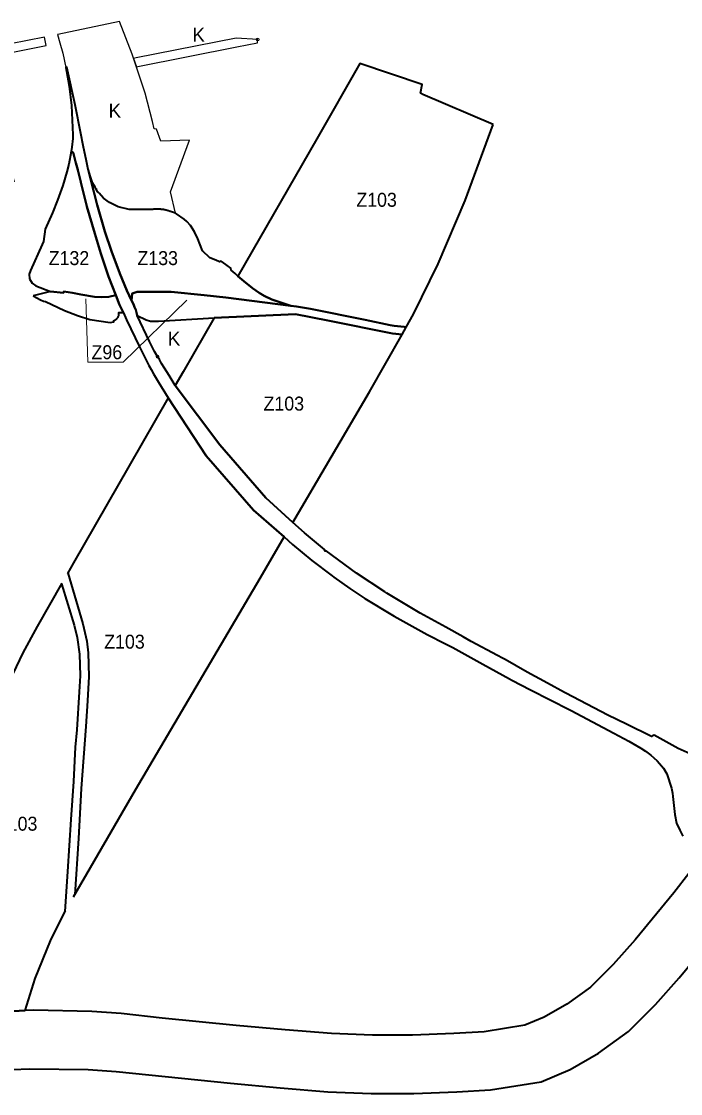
# Model space of a CAD drawing. Extents: x -650276 to -642489, y -1074311 to -1066658.
# Drawn here: x -647871 to -646740, y -1069094 to -1067254 of the extents above; entities that cross this region are included whole.
import ezdxf

# ---------------------------------------------------------------- set-up
doc = ezdxf.new("R2010")
doc.units = 0
doc.header["$LTSCALE"] = 9.6
doc.header["$PDMODE"] = 32
doc.header["$PDSIZE"] = 4.8
for name, color, linetype, lineweight in [('44', 7, 'Continuous', 40), ('47', 7, 'Continuous', 13), ('48', 7, 'Continuous', 13)]:
    doc.layers.add(name, color=color, linetype=linetype, lineweight=lineweight)

msp = doc.modelspace()

# ---------------------------------------------------------------- linework, layer by layer
at = {"layer": '44'}
for p, q in [((-647489.3, -1067700.07), (-647474.13, -1067711.81)), ((-647540.208, -1067762.876), (-647400.63, -1067756.19))]:
    msp.add_line(p, q, dxfattribs=at)
for points in [[(-647606.818, -1067879.061), (-647617.25, -1067861.95), (-647625.37, -1067848.86), (-647630.3, -1067841.02), (-647633.69, -1067834.31), (-647637.21, -1067829.29), (-647642.29, -1067820.76), (-647650.8, -1067803.28), (-647672.05, -1067758.98), (-647673.47, -1067753.48), (-647673.47, -1067753.48), (-647674.67, -1067748.73), (-647676.47, -1067744.5), (-647678.66, -1067739.38), (-647681.91, -1067732.74), (-647690.09, -1067716.05), (-647702.04, -1067686.86), (-647715.92, -1067648.12), (-647727.37, -1067614.33), (-647740.49, -1067568.67), (-647751.41, -1067526.58), (-647756.55, -1067505.32), (-647759.16, -1067494.01), (-647764.89, -1067466.64), (-647768.5, -1067446.04), (-647778.78, -1067397.1), (-647792.52, -1067332.74), (-647794.54, -1067333.14), (-647788.77, -1067365.03), (-647784.55, -1067398.01), (-647782.39, -1067448.34), (-647782.5, -1067455.11), (-647784.36, -1067469.6), (-647785.64, -1067477.02), (-647781.85, -1067479.19), (-647777.55, -1067496.95), (-647773.96, -1067508.48), (-647768.5, -1067529.75), (-647758.25, -1067571.79), (-647744.61, -1067617.96), (-647734.63, -1067652.57), (-647721.05, -1067691.73), (-647708.71, -1067723.99), (-647702.21, -1067740.43), (-647699.89, -1067745.24), (-647697.85, -1067749.46), (-647695.71, -1067753.9), (-647690.19, -1067766.37), (-647668.13, -1067812.76), (-647651.94, -1067844.36), (-647648.33, -1067851.17), (-647643.83, -1067859.13), (-647635.77, -1067873.43), (-647618.773, -1067899.914)], [(-647185.93, -1067377.38), (-647183.09, -1067362.16), (-647289.924, -1067326.309), (-647364.024, -1067455.561), (-647499.095, -1067691.163), (-647489.3, -1067700.07)], [(-647061.252, -1067430.908), (-647181.878, -1067379.12), (-647185.93, -1067377.38)], [(-647155.592, -1067670.17), (-647108.971, -1067561.55), (-647061.252, -1067430.908)], [(-647708.71, -1067723.99), (-647721.05, -1067691.73), (-647734.63, -1067652.57), (-647744.61, -1067617.96), (-647758.25, -1067571.79), (-647768.5, -1067529.75), (-647773.96, -1067508.48), (-647777.55, -1067496.95), (-647781.85, -1067479.19), (-647785.64, -1067477.02), (-647789.39, -1067498.84), (-647792.54, -1067511.85), (-647799.39, -1067535.48)], [(-647799.39, -1067535.48), (-647808.71, -1067561.03), (-647817.59, -1067582.4)], [(-647739.417, -1067547.032), (-647740.122, -1067546.264), (-647744.43, -1067538.658), (-647751.41, -1067526.58), (-647740.49, -1067568.67), (-647727.37, -1067614.33), (-647715.92, -1067648.12)], [(-647737.867, -1067548.624), (-647738.148, -1067548.252), (-647738.514, -1067547.9), (-647739.417, -1067547.032)], [(-647650.7, -1067576.803), (-647651.205, -1067576.828), (-647651.711, -1067576.853), (-647651.965, -1067576.865), (-647654.743, -1067576.996), (-647685.968, -1067576.68), (-647704.458, -1067572.034), (-647719.661, -1067564.884), (-647729.802, -1067557.462), (-647737.581, -1067548.996), (-647737.867, -1067548.624)], [(-647647.161, -1067576.624), (-647647.666, -1067576.65), (-647647.897, -1067576.661), (-647648.172, -1067576.675), (-647648.677, -1067576.701), (-647649.183, -1067576.727), (-647649.689, -1067576.752), (-647650.194, -1067576.778), (-647650.7, -1067576.803)], [(-647646.149, -1067576.572), (-647646.655, -1067576.598), (-647647.161, -1067576.624)], [(-647644.633, -1067576.496), (-647644.899, -1067576.509), (-647645.138, -1067576.521), (-647645.644, -1067576.546), (-647646.149, -1067576.572)], [(-647643.117, -1067576.424), (-647643.622, -1067576.447), (-647644.127, -1067576.471), (-647644.633, -1067576.496)], [(-647640.592, -1067576.322), (-647641.096, -1067576.34), (-647641.601, -1067576.359), (-647641.901, -1067576.371), (-647642.106, -1067576.38), (-647642.611, -1067576.401), (-647643.117, -1067576.424)], [(-647639.583, -1067576.291), (-647640.087, -1067576.306), (-647640.592, -1067576.322)], [(-647638.902, -1067576.275), (-647639.078, -1067576.278), (-647639.583, -1067576.291)], [(-647632.437, -1067576.408), (-647632.9, -1067576.39), (-647633.102, -1067576.383), (-647633.767, -1067576.357), (-647634.431, -1067576.331), (-647635.095, -1067576.305), (-647635.757, -1067576.28), (-647635.902, -1067576.274), (-647636.419, -1067576.254), (-647637.064, -1067576.246), (-647637.567, -1067576.251), (-647638.071, -1067576.258), (-647638.574, -1067576.267), (-647638.902, -1067576.275)], [(-647629.774, -1067576.618), (-647629.896, -1067576.607), (-647630.44, -1067576.557), (-647631.106, -1067576.502), (-647631.772, -1067576.452), (-647632.437, -1067576.408)], [(-647628.441, -1067576.759), (-647629.107, -1067576.685), (-647629.774, -1067576.618)], [(-647623.199, -1067577.752), (-647623.824, -1067577.594), (-647624.481, -1067577.461), (-647625.149, -1067577.324), (-647625.794, -1067577.193), (-647626.451, -1067577.059), (-647627.107, -1067576.926), (-647627.775, -1067576.839), (-647628.441, -1067576.759)], [(-647621.269, -1067578.278), (-647621.877, -1067578.106), (-647622.525, -1067577.929), (-647623.199, -1067577.752)], [(-647619.352, -1067578.859), (-647619.942, -1067578.674), (-647620.586, -1067578.478), (-647621.269, -1067578.278)], [(-647615.048, -1067580.385), (-647615.566, -1067580.184), (-647616.12, -1067579.975), (-647616.752, -1067579.743), (-647617.451, -1067579.494), (-647618.023, -1067579.297), (-647618.661, -1067579.083), (-647619.352, -1067578.859)], [(-647817.59, -1067582.4), (-647829.97, -1067610.62), (-647832.8, -1067631.53), (-647835.06, -1067637.01), (-647855.24, -1067681.26), (-647857.51, -1067687.74), (-647856.9, -1067695.97)], [(-647547.663, -1067659.519), (-647560.187, -1067647.458), (-647567.744, -1067627.24), (-647573.605, -1067614.951), (-647580.539, -1067604.432), (-647586.864, -1067597.411), (-647591.227, -1067593.613), (-647604.415, -1067584.047), (-647606.559, -1067583.309), (-647615.048, -1067580.385)], [(-647715.92, -1067648.12), (-647702.04, -1067686.86), (-647690.09, -1067716.05), (-647681.91, -1067732.74), (-647680.804, -1067720.745), (-647672, -1067718), (-647643, -1067718), (-647614, -1067718), (-647557, -1067724), (-647520.145, -1067727.879), (-647408.2, -1067742.37), (-647440.81, -1067731.38), (-647453.87, -1067724.97), (-647462.45, -1067719.84), (-647474.13, -1067711.81), (-647489.3, -1067700.07), (-647499.095, -1067691.163)], [(-647499.095, -1067691.163), (-647503.97, -1067686.73), (-647510.6, -1067680.86), (-647511.24, -1067677.53), (-647517.74, -1067672.85), (-647520.13, -1067671.13), (-647527.76, -1067665.65), (-647530.82, -1067666.65), (-647536.83, -1067663.64), (-647547.663, -1067659.519)], [(-647210.537, -1067778.594), (-647198.088, -1067756.5), (-647155.592, -1067670.17)], [(-647856.9, -1067695.97), (-647852.3, -1067703.36), (-647845.74, -1067707.59), (-647821.02, -1067717.33)], [(-647695.797, -1067753.719), (-647697.85, -1067749.46), (-647699.89, -1067745.24), (-647702.21, -1067740.43), (-647708.71, -1067723.99), (-647720.45, -1067726.49), (-647732.71, -1067727.02), (-647745.41, -1067726.6), (-647768.53, -1067722.82), (-647783.13, -1067719.68), (-647798.17, -1067717.58), (-647798.5, -1067719.67), (-647821.02, -1067717.33), (-647850.45, -1067724.77)], [(-647850.45, -1067724.77), (-647838.18, -1067731.62), (-647832.56, -1067734.22), (-647829.49, -1067734.58), (-647796.87, -1067750.25), (-647774.54, -1067758.68), (-647753.53, -1067765.58), (-647718.54, -1067770.6), (-647712.01, -1067769.63), (-647712.26, -1067767.28)], [(-647821.02, -1067717.33), (-647798.5, -1067719.67), (-647798.17, -1067717.58), (-647783.13, -1067719.68), (-647768.53, -1067722.82), (-647745.41, -1067726.6), (-647732.71, -1067727.02), (-647720.45, -1067726.49), (-647708.71, -1067723.99)], [(-647520.145, -1067727.879), (-647557, -1067724), (-647614, -1067718), (-647643, -1067718), (-647672, -1067718), (-647680.804, -1067720.745), (-647681.91, -1067732.74)], [(-647474.13, -1067711.81), (-647462.45, -1067719.84), (-647453.87, -1067724.97), (-647440.81, -1067731.38), (-647408.2, -1067742.37), (-647398.74, -1067743.15)], [(-647681.91, -1067732.74), (-647678.66, -1067739.38), (-647676.47, -1067744.5), (-647674.67, -1067748.73), (-647673.47, -1067753.48)], [(-647398.74, -1067743.15), (-647408.2, -1067742.37), (-647520.145, -1067727.879)], [(-647210.537, -1067778.594), (-647213.92, -1067778.26), (-647231.17, -1067776.55), (-647237.91, -1067775.18), (-647280.78, -1067766.44), (-647374.55, -1067747.34), (-647398.74, -1067743.15)], [(-647398.74, -1067743.15), (-647374.55, -1067747.34), (-647280.78, -1067766.44), (-647237.91, -1067775.18), (-647231.17, -1067776.55), (-647213.92, -1067778.26), (-647210.537, -1067778.594)], [(-647712.26, -1067767.28), (-647711.773, -1067767.135), (-647711.286, -1067766.968), (-647710.799, -1067766.777), (-647710.315, -1067766.562), (-647709.834, -1067766.324), (-647709.359, -1067766.062), (-647708.892, -1067765.776), (-647708.433, -1067765.466), (-647707.985, -1067765.133), (-647707.55, -1067764.777), (-647707.128, -1067764.398), (-647706.723, -1067763.999), (-647706.335, -1067763.579), (-647705.966, -1067763.14), (-647705.617, -1067762.683), (-647705.29, -1067762.21), (-647704.985, -1067761.721), (-647704.704, -1067761.22), (-647704.447, -1067760.707), (-647704.216, -1067760.184), (-647704.01, -1067759.653), (-647703.83, -1067759.117), (-647703.675, -1067758.576), (-647703.547, -1067758.033), (-647703.445, -1067757.489), (-647703.368, -1067756.946), (-647703.315, -1067756.406), (-647703.287, -1067755.87), (-647703.282, -1067755.341), (-647703.3, -1067754.818), (-647703.34, -1067754.304), (-647703.4, -1067753.8), (-647695.797, -1067753.719)], [(-647673.47, -1067753.48), (-647672.05, -1067758.98), (-647672.05, -1067758.98), (-647656.469, -1067766.309), (-647649.22, -1067768.38), (-647635.758, -1067768.38), (-647540.208, -1067762.876)], [(-647540.208, -1067762.876), (-647593.267, -1067855.425), (-647606.818, -1067879.061)], [(-647217.611, -1067791.149), (-647233.83, -1067789.69), (-647345.11, -1067767.28), (-647400.63, -1067756.19), (-647540.208, -1067762.876)], [(-647400.63, -1067756.19), (-647345.11, -1067767.28), (-647233.83, -1067789.69), (-647217.611, -1067791.149), (-647210.537, -1067778.594)], [(-647405.026, -1068113.904), (-647273.297, -1067889.981), (-647217.611, -1067791.149)], [(-647405.026, -1068113.904), (-647451.024, -1068071.886), (-647530.038, -1067980.839), (-647606.818, -1067879.061)], [(-647606.818, -1067879.061), (-647530.038, -1067980.839), (-647451.024, -1068071.886), (-647405.026, -1068113.904)], [(-647618.773, -1067899.914), (-647685.819, -1068016.861), (-647781.346, -1068183.485), (-647791.669, -1068201.583)], [(-647781.204, -1068756.329), (-647675.054, -1068572.919), (-647461.188, -1068209.373), (-647419.713, -1068138.871), (-647472.338, -1068093.096), (-647553.628, -1067999.427), (-647618.773, -1067899.915), (-647618.773, -1067899.914)], [(-647618.773, -1067899.914), (-647553.628, -1067999.427), (-647472.338, -1068093.096), (-647419.713, -1068138.871)], [(-646686.84, -1068526.89), (-646743.69, -1068501.76), (-646785.05, -1068479.12), (-646787.55, -1068480.36), (-646789.49, -1068481.31), (-646832.29, -1068460.04), (-646864.48, -1068444.64), (-646936.47, -1068407.23), (-646938.95, -1068405.8), (-646967.64, -1068390), (-647002.71, -1068371.09), (-647040.77, -1068349.4), (-647044.93, -1068347.08), (-647053.75, -1068342.11), (-647099.2, -1068318.27), (-647112.813, -1068310.564), (-647142.41, -1068293.81), (-647186.26, -1068269.45), (-647243.39, -1068235.26), (-647246.8, -1068233.08), (-647295.47, -1068201.09), (-647347.74, -1068162.54), (-647349.59, -1068163.24), (-647350.6, -1068160.26), (-647353.81, -1068157.67), (-647385.13, -1068131.51), (-647405.026, -1068113.904)], [(-647419.713, -1068138.871), (-647405.71, -1068151.74), (-647372.38, -1068179.01), (-647337.74, -1068205.67), (-647334.62, -1068208.02), (-647307.39, -1068227.44), (-647281.64, -1068244.34), (-647234.11, -1068273.04), (-647230.83, -1068274.93), (-647174.56, -1068306.35), (-647142.788, -1068322.462), (-647130.29, -1068328.8), (-647079.16, -1068357.01), (-647032.91, -1068382.51), (-647029.23, -1068384.46), (-646997.06, -1068401.37), (-646929.56, -1068435.42), (-646927.06, -1068436.66)], [(-647791.055, -1068200.507), (-647765.22, -1068287.94), (-647758.45, -1068317.66), (-647756.09, -1068337.61), (-647754.99, -1068378.21), (-647757.41, -1068419.98), (-647760.22, -1068463.96), (-647768.02, -1068570.36), (-647772.85, -1068656.41), (-647778.967, -1068752.463)], [(-647801.168, -1068218.237), (-647843.6, -1068292.629), (-647868.214, -1068337.803), (-647914.339, -1068432.512), (-647946.187, -1068510.254), (-647971.074, -1068581.98), (-647997.27, -1068674.747), (-648011.775, -1068739.718), (-648023.914, -1068809.332), (-648030.73, -1068861.213), (-648038.596, -1068968.281), (-647958.168, -1068957.73)], [(-647801.797, -1068219.339), (-647780.07, -1068290.53), (-647774.94, -1068311.47), (-647770.81, -1068340.29), (-647770.12, -1068377.5), (-647771.74, -1068404.5), (-647775.82, -1068469.74), (-647778.24, -1068499.95), (-647781.55, -1068558.38), (-647785.79, -1068623.98), (-647791.77, -1068713.23), (-647796.139, -1068781.67)], [(-646927.06, -1068436.66), (-646854.18, -1068475.8), (-646828.2, -1068489.61), (-646807.82, -1068501.17), (-646799.79, -1068506.39), (-646790.66, -1068513.24), (-646785.34, -1068517.77), (-646779.93, -1068522.9), (-646775.44, -1068527.74), (-646768.95, -1068535.8), (-646763.1, -1068545.18), (-646754.92, -1068569.81), (-646753.35, -1068578.6), (-646752.59, -1068584.55), (-646749.35, -1068615.18), (-646746.32, -1068630.23), (-646740.91, -1068642.34), (-646735.62, -1068652.21)], [(-646704.316, -1068689.698), (-646725.374, -1068716.786), (-646751.116, -1068749.975), (-646817.718, -1068830.545), (-646855.506, -1068872.883), (-646894.206, -1068911.595), (-646934.465, -1068940.759)], [(-647065.688, -1069087.73), (-646978.92, -1069073.93), (-646929.186, -1069052.925), (-646880.163, -1069024.903), (-646829.104, -1068987.917), (-646782.784, -1068941.581), (-646741.85, -1068895.719), (-646673.05, -1068812.491), (-646618.655, -1068742.359), (-646617.991, -1068741.504)], [(-647864.531, -1068951.823), (-647846.989, -1068896.545), (-647820.883, -1068832.117), (-647797.632, -1068784.713), (-647795.185, -1068780.485)], [(-646934.465, -1068940.759), (-646973.61, -1068963.135), (-647006.63, -1068977.08), (-647076.422, -1068988.18), (-647128.674, -1068991.167), (-647199.672, -1068994.255), (-647268.348, -1068994.255), (-647338.816, -1068991.19), (-647417.895, -1068984.986), (-647502.412, -1068977.157), (-647629.424, -1068964.608), (-647699.561, -1068956.635), (-647749.978, -1068953.416)], [(-647749.978, -1068953.416), (-647850.043, -1068951.099), (-647864.531, -1068951.823), (-647895.901, -1068953.392), (-647958.168, -1068957.73), (-648038.596, -1068968.281), (-648038.596, -1068968.281), (-648038.746, -1068968.301), (-648058.764, -1068970.927)], [(-647958.168, -1068957.73), (-647895.901, -1068953.392), (-647864.531, -1068951.823)], [(-647886.615, -1069053.052), (-647856.541, -1069051.548), (-647756.441, -1069053.207), (-647708.401, -1069056.275), (-647511.94, -1069076.703), (-647426.417, -1069084.624), (-647344.902, -1069091.02), (-647270.522, -1069094.255), (-647197.498, -1069094.255), (-647123.648, -1069091.043), (-647065.688, -1069087.73)]]:
    msp.add_lwpolyline(points, dxfattribs=at)
at = {"layer": '44', "lineweight": 13}
msp.add_lwpolyline([(-647586.774, -1067732.166), (-647696.17, -1067839.096), (-647756.708, -1067839.096), (-647760.132, -1067730.33)], dxfattribs=at)
at = {"layer": '47', "lineweight": 25}
for p, q in [((-647740.124, -1067546.265), (-647739.417, -1067547.032)), ((-647740, -1067546.181), (-647739.998, -1067546.18)), ((-647640.591, -1067576.33), (-647640.087, -1067576.306))]:
    msp.add_line(p, q, dxfattribs=at)
for points in [[(-647638.68, -1067439.06), (-647642.686, -1067438.46), (-647645.78, -1067425.81), (-647658.13, -1067376.99), (-647680.64, -1067310.37), (-647702.42, -1067253.98), (-647808.25, -1067276.11), (-647809.02, -1067276.27), (-647804.823, -1067290.788)], [(-647882.66, -1067529.231), (-647926.759, -1067358.379), (-647937.355, -1067316.774), (-647828.376, -1067295.406), (-647828.104, -1067295.352), (-647831.28, -1067280.69), (-647948.488, -1067303.671)], [(-647465.203, -1067285.115), (-647501.968, -1067282.642), (-647673.685, -1067316.666), (-647678.21, -1067317.562), (-647673.367, -1067331.895), (-647670.77, -1067331.38), (-647501.099, -1067297.762)], [(-647501.099, -1067297.762), (-647465.699, -1067290.747), (-647465.203, -1067285.115)], [(-647804.823, -1067290.788), (-647799.76, -1067308.3), (-647794.54, -1067333.14)], [(-647794.54, -1067333.14), (-647792.52, -1067332.74), (-647778.78, -1067397.1), (-647768.5, -1067446.04)], [(-647768.5, -1067446.04), (-647764.89, -1067466.64), (-647759.16, -1067494.01), (-647756.55, -1067505.32), (-647755.255, -1067510.676)], [(-647615.048, -1067580.385), (-647606.559, -1067583.309), (-647614.75, -1067546.53), (-647582.2, -1067457.65), (-647631.59, -1067459.72), (-647638.68, -1067439.06)], [(-647755.255, -1067510.676), (-647755.159, -1067511.027), (-647754.116, -1067514.604)], [(-647754.116, -1067514.604), (-647753.006, -1067518.156), (-647751.818, -1067521.68), (-647750.545, -1067525.169), (-647749.178, -1067528.619), (-647747.708, -1067532.022), (-647746.127, -1067535.371), (-647744.43, -1067538.658), (-647740.122, -1067546.264)], [(-647742.158, -1067541.404), (-647741.902, -1067541.247), (-647741.647, -1067541.09), (-647740.804, -1067541.512), (-647742.167, -1067542.348)], [(-647739.998, -1067546.18), (-647742.045, -1067542.565), (-647742.167, -1067542.348), (-647742.158, -1067541.404)], [(-647742.167, -1067542.348), (-647742.037, -1067542.56), (-647741.936, -1067542.723), (-647741.743, -1067543.03), (-647741.67, -1067543.146), (-647741.447, -1067543.497), (-647741.402, -1067543.568), (-647741.148, -1067543.963), (-647741.132, -1067543.989), (-647740.859, -1067544.408), (-647740.846, -1067544.427), (-647740.583, -1067544.825), (-647740.541, -1067544.889), (-647740.519, -1067544.919), (-647740.333, -1067545.195), (-647740.265, -1067545.295), (-647740.068, -1067545.582), (-647739.971, -1067545.724), (-647739.801, -1067545.968), (-647739.674, -1067546.15), (-647739.532, -1067546.353), (-647739.504, -1067546.391), (-647739.374, -1067546.575), (-647739.26, -1067546.736), (-647739.072, -1067546.998), (-647738.986, -1067547.117), (-647738.767, -1067547.418), (-647738.709, -1067547.496), (-647738.456, -1067547.839), (-647738.431, -1067547.874), (-647738.148, -1067548.252), (-647737.867, -1067548.624), (-647737.834, -1067548.667), (-647737.581, -1067548.996), (-647737.518, -1067549.078)], [(-647739.966, -1067546.23), (-647739.968, -1067546.231), (-647739.983, -1067546.206)], [(-647737.525, -1067549.085), (-647729.802, -1067557.462), (-647719.661, -1067564.884), (-647704.458, -1067572.034), (-647685.968, -1067576.68)], [(-647685.968, -1067576.68), (-647654.743, -1067576.996), (-647651.965, -1067576.865)], [(-647651.965, -1067576.865), (-647651.711, -1067576.853), (-647651.205, -1067576.828), (-647650.7, -1067576.803), (-647650.194, -1067576.778), (-647649.689, -1067576.752), (-647649.183, -1067576.727), (-647648.677, -1067576.701), (-647648.172, -1067576.675), (-647647.897, -1067576.661), (-647647.666, -1067576.65), (-647647.161, -1067576.624), (-647646.655, -1067576.598), (-647646.149, -1067576.572), (-647645.644, -1067576.546), (-647645.138, -1067576.521), (-647644.899, -1067576.509), (-647644.633, -1067576.496), (-647644.127, -1067576.471), (-647643.622, -1067576.447), (-647643.117, -1067576.424), (-647642.611, -1067576.401), (-647642.106, -1067576.38), (-647641.901, -1067576.371), (-647641.601, -1067576.359), (-647641.096, -1067576.34), (-647640.592, -1067576.322)], [(-647640.087, -1067576.306), (-647639.583, -1067576.291), (-647639.078, -1067576.278), (-647638.902, -1067576.275), (-647638.574, -1067576.267), (-647638.071, -1067576.258), (-647637.567, -1067576.251), (-647637.064, -1067576.246), (-647637.01, -1067576.246), (-647636.419, -1067576.254), (-647635.902, -1067576.265), (-647635.757, -1067576.268), (-647635.094, -1067576.286), (-647635.037, -1067576.288), (-647634.431, -1067576.309), (-647633.767, -1067576.337), (-647633.102, -1067576.37), (-647633.058, -1067576.372), (-647632.9, -1067576.382), (-647632.437, -1067576.408), (-647631.772, -1067576.452), (-647631.106, -1067576.502), (-647631.076, -1067576.504), (-647630.44, -1067576.557), (-647629.896, -1067576.607), (-647629.774, -1067576.618), (-647629.107, -1067576.685), (-647629.091, -1067576.687), (-647628.441, -1067576.759), (-647627.775, -1067576.839), (-647627.107, -1067576.926), (-647626.443, -1067577.019), (-647625.783, -1067577.139), (-647625.14, -1067577.282), (-647625.129, -1067577.284), (-647624.476, -1067577.436), (-647623.824, -1067577.594), (-647623.199, -1067577.752), (-647623.174, -1067577.759), (-647622.525, -1067577.929), (-647621.877, -1067578.106), (-647621.269, -1067578.278), (-647621.23, -1067578.289), (-647620.586, -1067578.478), (-647619.942, -1067578.674), (-647619.352, -1067578.859), (-647619.301, -1067578.875), (-647618.661, -1067579.083), (-647618.023, -1067579.297), (-647617.451, -1067579.494), (-647617.387, -1067579.517), (-647616.752, -1067579.743), (-647616.12, -1067579.975), (-647615.566, -1067580.184), (-647615.489, -1067580.214), (-647615.048, -1067580.385)]]:
    msp.add_lwpolyline(points, dxfattribs=at)
at = {"layer": '47'}
msp.add_lwpolyline([(-647606.818, -1067879.061), (-647540.208, -1067762.876), (-647635.758, -1067768.38), (-647649.22, -1067768.38), (-647656.469, -1067766.309), (-647672.05, -1067758.98), (-647650.8, -1067803.28), (-647642.29, -1067820.76), (-647637.21, -1067829.29), (-647633.69, -1067834.31), (-647630.3, -1067841.02), (-647625.37, -1067848.86), (-647617.25, -1067861.95)], close=True, dxfattribs=at)
at = {"layer": '47', "lineweight": 25}
for start, end in [(214.04927, 214.0695), (214.08975, 214.75472)]:
    msp.add_arc((-647670.608, -1067499.289), 83.75, start, end, dxfattribs=at)
at = {"layer": '47'}
for p in [(-647465.203, -1067285.115), (-647637.21, -1067829.29)]:
    msp.add_point(p, dxfattribs=at)

# ---------------------------------------------------------------- texts
at = {"layer": '44', "width": 0.95}
for s, p in [('Z103', (-647295.975, -1067572.121)), ('Z103', (-647295.975, -1067572.121)), ('Z132', (-647823.879, -1067672.215)), ('Z133', (-647671.579, -1067672.215)), ('Z96', (-647750.408, -1067833.749)), ('Z103', (-647455.179, -1067921.933)), ('Z103', (-647455.179, -1067921.933)), ('Z103', (-647728.595, -1068330.624)), ('Z103', (-647728.595, -1068330.624)), ('Z103', (-647912.849, -1068643.055))]:
    msp.add_text(s, height=24, dxfattribs=at).set_placement(p)
at = {"layer": '48'}
for p in [(-647577.244, -1067288.889), (-647721.126, -1067419.035), (-647619.44, -1067810.434)]:
    msp.add_text('K', height=24, dxfattribs=at).set_placement(p)

doc.saveas('drawing.dxf')
